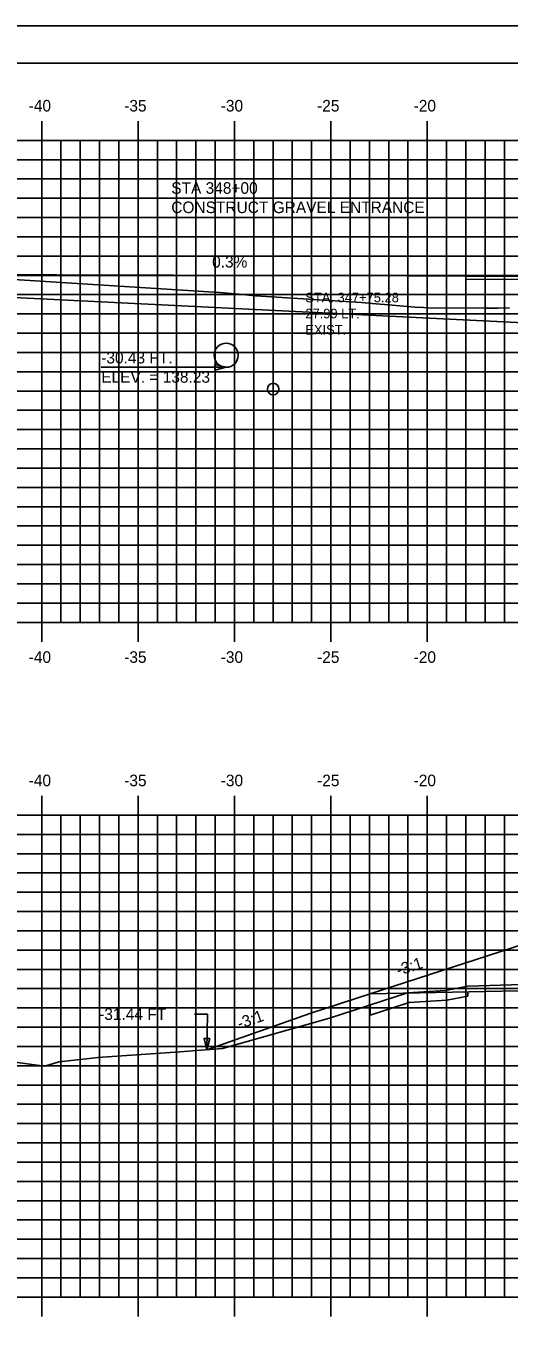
# Model space of a CAD drawing. Extents: x 1144085 to 1144255, y 608981 to 609091.
# Drawn here: x 1144127.5 to 1144152.6, y 609024.1 to 609091.3 of the extents above; entities that cross this region are included whole.
import ezdxf

# ---------------------------------------------------------------- set-up
doc = ezdxf.new("R2010")
doc.units = 0
for name, color, linetype in [('ANNOTATION', 7, 'Continuous'), ('BORDER', 7, 'Continuous'), ('D_Drainage_Culvert', 7, 'Continuous'), ('D_Roadway_Edge_Shoulder', 7, 'Continuous'), ('D_Roadway_SlopeLines', 7, 'Continuous'), ('D_Roadway_SubGrade', 7, 'Continuous'), ('D_Text_Monospaced', 7, 'Continuous'), ('D_Text_Standard', 7, 'Continuous'), ('H_V ANNOTATION', 7, 'Continuous'), ('MAJOR', 7, 'Continuous'), ('MINOR', 7, 'Continuous'), ('PLOT BOUNDARY', 7, 'Continuous'), ('S_Drainage_Invert', 7, 'Continuous'), ('S_Roadway_Centerline', 7, 'Continuous')]:
    doc.layers.add(name, color=color, linetype=linetype)

msp = doc.modelspace()

# ---------------------------------------------------------------- linework, layer by layer
for points in [[(1144123.068, 609078.385), (1144153.349, 609078.292), (1144157.349, 609078.452), (1144168.349, 609078.672), (1144179.349, 609078.452), (1144188.751, 609078.076), (1144196.129, 609075.617), (1144199.129, 609074.617), (1144217.63, 609068.45)], [(1144136.907, 609038.164), (1144142.311, 609040.063), (1144145.395, 609041.063), (1144153.348, 609043.642), (1144153.349, 609043.642), (1144157.349, 609043.802), (1144168.349, 609044.022), (1144179.349, 609043.802), (1144190.025, 609043.375), (1144197.322, 609040.943), (1144200.322, 609039.943), (1144215.637, 609034.838)]]:
    msp.add_lwpolyline(points)
at = {"layer": 'BORDER'}
msp.add_lwpolyline([(1144093.349, 608984.335), (1144253.349, 608984.335), (1144253.349, 609089.335), (1144093.349, 609089.335)], close=True, dxfattribs=at)
at = {"layer": 'D_Drainage_Culvert'}
msp.add_circle((1144137.919, 609074.19), 0.625, dxfattribs=at)
at = {"layer": 'D_Roadway_Edge_Shoulder'}
msp.add_lwpolyline([(1144153.349, 609078.292), (1144150.349, 609078.301), (1144150.349, 609078.135), (1144153.349, 609078.126)], close=True, dxfattribs=at)
at = {"layer": 'D_Roadway_SlopeLines'}
for p, q in [((1144150.45, 609041.164), (1144150.45, 609040.948)), ((1144145.395, 609040.49), (1144145.395, 609039.966))]:
    msp.add_line(p, q, dxfattribs=at)
for points in [[(1144145.395, 609041.063), (1144142.311, 609040.063)], [(1144145.395, 609039.966), (1144147.415, 609040.623), (1144149.357, 609040.737), (1144150.45, 609040.948)], [(1144142.311, 609040.063), (1144136.907, 609038.164)]]:
    msp.add_lwpolyline(points, dxfattribs=at)
at = {"layer": 'D_Roadway_SubGrade'}
for points in [[(1144123.068, 609077.385), (1144153.349, 609075.872), (1144157.349, 609075.952), (1144157.349, 609078.036), (1144157.349, 609078.202), (1144153.349, 609078.042), (1144153.349, 609078.292), (1144123.068, 609078.385)], [(1144157.349, 609043.386), (1144157.349, 609043.552), (1144153.349, 609043.392), (1144153.349, 609043.642), (1144153.348, 609043.642), (1144145.395, 609041.063), (1144157.349, 609041.302)]]:
    msp.add_lwpolyline(points, close=True, dxfattribs=at)
at = {"layer": 'D_Text_Standard'}
msp.add_line((1144131.438, 609073.565), (1144136.238, 609073.565), dxfattribs=at)
for points in [[(1144137.919, 609073.565), (1144136.918, 609073.565), (1144136.238, 609073.565)], [(1144136.907, 609038.164), (1144136.95, 609040.013), (1144136.27, 609040.013)]]:
    msp.add_lwpolyline(points, dxfattribs=at)
for points in [[(1144137.919, 609073.565), (1144137.337, 609073.42), (1144137.337, 609073.711)], [(1144136.907, 609038.164), (1144136.775, 609038.749), (1144137.066, 609038.742)]]:
    msp.add_lwpolyline(points, close=True, dxfattribs=at)
at = {"layer": 'MAJOR'}
for p, q in [((1144128.349, 609086.337), (1144128.349, 609085.335)), ((1144133.349, 609086.337), (1144133.349, 609085.335)), ((1144138.349, 609086.337), (1144138.349, 609085.335)), ((1144143.349, 609086.337), (1144143.349, 609085.335)), ((1144148.349, 609086.337), (1144148.349, 609085.335)), ((1144098.349, 609085.335), (1144238.349, 609085.335)), ((1144098.349, 609085.335), (1144238.349, 609085.335)), ((1144128.349, 609060.335), (1144128.349, 609085.335)), ((1144133.349, 609060.335), (1144133.349, 609085.335)), ((1144138.349, 609060.335), (1144138.349, 609085.335)), ((1144143.349, 609060.335), (1144143.349, 609085.335)), ((1144148.349, 609060.335), (1144148.349, 609085.335)), ((1144098.349, 609080.335), (1144238.349, 609080.335)), ((1144098.349, 609075.335), (1144238.349, 609075.335)), ((1144098.349, 609070.335), (1144238.349, 609070.335)), ((1144098.349, 609065.335), (1144238.349, 609065.335)), ((1144098.349, 609060.335), (1144238.349, 609060.335)), ((1144098.349, 609060.335), (1144238.349, 609060.335)), ((1144128.349, 609059.333), (1144128.349, 609060.335)), ((1144133.349, 609059.333), (1144133.349, 609060.335)), ((1144138.349, 609059.333), (1144138.349, 609060.335)), ((1144143.349, 609059.333), (1144143.349, 609060.335)), ((1144148.349, 609059.333), (1144148.349, 609060.335)), ((1144128.349, 609051.337), (1144128.349, 609050.335)), ((1144133.349, 609051.337), (1144133.349, 609050.335)), ((1144138.349, 609051.337), (1144138.349, 609050.335)), ((1144143.349, 609051.337), (1144143.349, 609050.335)), ((1144148.349, 609051.337), (1144148.349, 609050.335)), ((1144098.349, 609050.335), (1144238.349, 609050.335)), ((1144098.349, 609050.335), (1144238.349, 609050.335)), ((1144128.349, 609025.335), (1144128.349, 609050.335)), ((1144133.349, 609025.335), (1144133.349, 609050.335)), ((1144138.349, 609025.335), (1144138.349, 609050.335)), ((1144143.349, 609025.335), (1144143.349, 609050.335)), ((1144148.349, 609025.335), (1144148.349, 609050.335)), ((1144098.349, 609045.335), (1144238.349, 609045.335)), ((1144098.349, 609040.335), (1144238.349, 609040.335)), ((1144098.349, 609035.335), (1144238.349, 609035.335)), ((1144098.349, 609030.335), (1144238.349, 609030.335)), ((1144098.349, 609025.335), (1144238.349, 609025.335)), ((1144098.349, 609025.335), (1144238.349, 609025.335)), ((1144128.349, 609024.333), (1144128.349, 609025.335)), ((1144133.349, 609024.333), (1144133.349, 609025.335)), ((1144138.349, 609024.333), (1144138.349, 609025.335)), ((1144143.349, 609024.333), (1144143.349, 609025.335)), ((1144148.349, 609024.333), (1144148.349, 609025.335))]:
    msp.add_line(p, q, dxfattribs=at)
at = {"layer": 'MINOR'}
for p, q in [((1144129.349, 609060.335), (1144129.349, 609085.335)), ((1144130.349, 609060.335), (1144130.349, 609085.335)), ((1144131.349, 609060.335), (1144131.349, 609085.335)), ((1144132.349, 609060.335), (1144132.349, 609085.335)), ((1144134.349, 609060.335), (1144134.349, 609085.335)), ((1144135.349, 609060.335), (1144135.349, 609085.335)), ((1144136.349, 609060.335), (1144136.349, 609085.335)), ((1144137.349, 609060.335), (1144137.349, 609085.335)), ((1144139.349, 609060.335), (1144139.349, 609085.335)), ((1144140.349, 609060.335), (1144140.349, 609085.335)), ((1144141.349, 609060.335), (1144141.349, 609085.335)), ((1144142.349, 609060.335), (1144142.349, 609085.335)), ((1144144.349, 609060.335), (1144144.349, 609085.335)), ((1144145.349, 609060.335), (1144145.349, 609085.335)), ((1144146.349, 609060.335), (1144146.349, 609085.335)), ((1144147.349, 609060.335), (1144147.349, 609085.335)), ((1144149.349, 609060.335), (1144149.349, 609085.335)), ((1144150.349, 609060.335), (1144150.349, 609085.335)), ((1144151.349, 609060.335), (1144151.349, 609085.335)), ((1144152.349, 609060.335), (1144152.349, 609085.335)), ((1144098.349, 609084.335), (1144238.349, 609084.335)), ((1144098.349, 609083.335), (1144238.349, 609083.335)), ((1144098.349, 609082.335), (1144238.349, 609082.335)), ((1144098.349, 609081.335), (1144238.349, 609081.335)), ((1144098.349, 609079.335), (1144238.349, 609079.335)), ((1144098.349, 609078.335), (1144238.349, 609078.335)), ((1144098.349, 609077.335), (1144238.349, 609077.335)), ((1144098.349, 609076.335), (1144238.349, 609076.335)), ((1144098.349, 609074.335), (1144238.349, 609074.335)), ((1144098.349, 609073.335), (1144238.349, 609073.335)), ((1144098.349, 609072.335), (1144238.349, 609072.335)), ((1144098.349, 609071.335), (1144238.349, 609071.335)), ((1144098.349, 609069.335), (1144238.349, 609069.335)), ((1144098.349, 609068.335), (1144238.349, 609068.335)), ((1144098.349, 609067.335), (1144238.349, 609067.335)), ((1144098.349, 609066.335), (1144238.349, 609066.335)), ((1144098.349, 609064.335), (1144238.349, 609064.335)), ((1144098.349, 609063.335), (1144238.349, 609063.335)), ((1144098.349, 609062.335), (1144238.349, 609062.335)), ((1144098.349, 609061.335), (1144238.349, 609061.335)), ((1144129.349, 609025.335), (1144129.349, 609050.335)), ((1144130.349, 609025.335), (1144130.349, 609050.335)), ((1144131.349, 609025.335), (1144131.349, 609050.335)), ((1144132.349, 609025.335), (1144132.349, 609050.335)), ((1144134.349, 609025.335), (1144134.349, 609050.335)), ((1144135.349, 609025.335), (1144135.349, 609050.335)), ((1144136.349, 609025.335), (1144136.349, 609050.335)), ((1144137.349, 609025.335), (1144137.349, 609050.335)), ((1144139.349, 609025.335), (1144139.349, 609050.335)), ((1144140.349, 609025.335), (1144140.349, 609050.335)), ((1144141.349, 609025.335), (1144141.349, 609050.335)), ((1144142.349, 609025.335), (1144142.349, 609050.335)), ((1144144.349, 609025.335), (1144144.349, 609050.335)), ((1144145.349, 609025.335), (1144145.349, 609050.335)), ((1144146.349, 609025.335), (1144146.349, 609050.335)), ((1144147.349, 609025.335), (1144147.349, 609050.335)), ((1144149.349, 609025.335), (1144149.349, 609050.335)), ((1144150.349, 609025.335), (1144150.349, 609050.335)), ((1144151.349, 609025.335), (1144151.349, 609050.335)), ((1144152.349, 609025.335), (1144152.349, 609050.335)), ((1144098.349, 609049.335), (1144238.349, 609049.335)), ((1144098.349, 609048.335), (1144238.349, 609048.335)), ((1144098.349, 609047.335), (1144238.349, 609047.335)), ((1144098.349, 609046.335), (1144238.349, 609046.335)), ((1144098.349, 609044.335), (1144238.349, 609044.335)), ((1144098.349, 609043.335), (1144238.349, 609043.335)), ((1144098.349, 609042.335), (1144238.349, 609042.335)), ((1144098.349, 609041.335), (1144238.349, 609041.335)), ((1144098.349, 609039.335), (1144238.349, 609039.335)), ((1144098.349, 609038.335), (1144238.349, 609038.335)), ((1144098.349, 609037.335), (1144238.349, 609037.335)), ((1144098.349, 609036.335), (1144238.349, 609036.335)), ((1144098.349, 609034.335), (1144238.349, 609034.335)), ((1144098.349, 609033.335), (1144238.349, 609033.335)), ((1144098.349, 609032.335), (1144238.349, 609032.335)), ((1144098.349, 609031.335), (1144238.349, 609031.335)), ((1144098.349, 609029.335), (1144238.349, 609029.335)), ((1144098.349, 609028.335), (1144238.349, 609028.335)), ((1144098.349, 609027.335), (1144238.349, 609027.335)), ((1144098.349, 609026.335), (1144238.349, 609026.335))]:
    msp.add_line(p, q, dxfattribs=at)
at = {"layer": 'PLOT BOUNDARY'}
msp.add_lwpolyline([(1144085.256, 608981.276), (1144255.256, 608981.276), (1144255.256, 609091.276), (1144085.256, 609091.276)], close=True, dxfattribs=at)
at = {"layer": 'S_Drainage_Invert'}
msp.add_circle((1144140.359, 609072.44), 0.3, dxfattribs=at)
at = {"layer": 'S_Roadway_Centerline'}
for points in [[(1144126.071, 609078.177), (1144137.012, 609077.48), (1144137.577, 609077.438), (1144138.591, 609077.353), (1144139.444, 609077.274), (1144144.945, 609076.93), (1144145.68, 609076.863), (1144146.127, 609076.822), (1144146.92, 609076.752), (1144147.725, 609076.691), (1144148.16, 609076.665), (1144148.408, 609076.655), (1144151.408, 609076.635), (1144152.016, 609076.628), (1144152.614, 609076.656)], [(1144126.454, 609037.587), (1144128.501, 609037.315), (1144129.255, 609037.532), (1144130.973, 609037.736), (1144131.266, 609037.758), (1144135.518, 609038.06), (1144137.734, 609038.225), (1144143.271, 609039.799), (1144147.322, 609041.116), (1144149.295, 609041.232), (1144150.45, 609041.455), (1144156.669, 609041.645), (1144161.807, 609041.922), (1144167.699, 609041.655), (1144172.025, 609041.53), (1144174.185, 609041.13), (1144175.974, 609040.912), (1144181.368, 609038.355), (1144184.046, 609037.211), (1144194.528, 609036.383), (1144201.114, 609035.654)]]:
    msp.add_lwpolyline(points, dxfattribs=at)

# ---------------------------------------------------------------- texts
at = {"layer": 'ANNOTATION'}
for s, p in [('STA 348+00', (1144135.07, 609082.567)), ('CONSTRUCT GRAVEL ENTRANCE', (1144135.07, 609081.565))]:
    msp.add_text(s, height=0.6, dxfattribs=at).set_placement(p)
for s, rotation, p in [('0.3%', 359.8252, (1144137.19, 609078.742)), ('-3:1', 17.96614, (1144146.853, 609041.987)), ('-3:1', 19.36486, (1144138.614, 609039.224))]:
    msp.add_text(s, height=0.6, rotation=rotation, dxfattribs=at).set_placement(p)
at = {"layer": 'D_Text_Monospaced'}
for s, height, p in [('STA. 347+75.28', 0.49998, (1144142.026, 609076.938)), ('27.99 LT.', 0.5, (1144142.026, 609076.104)), ('EXIST. ', 0.5, (1144142.026, 609075.264))]:
    msp.add_text(s, height=height, dxfattribs=at).set_placement(p)
at = {"layer": 'D_Text_Standard'}
for s, p in [('-30.43 FT.', (1144131.438, 609073.765)), ('ELEV. = 138.23', (1144131.438, 609072.765)), ('-31.44 FT', (1144131.33, 609039.713))]:
    msp.add_text(s, height=0.6, dxfattribs=at).set_placement(p)
at = {"layer": 'H_V ANNOTATION'}
for s, p in [('-40', (1144127.675, 609086.835)), ('-35', (1144132.629, 609086.835)), ('-30', (1144137.637, 609086.835)), ('-25', (1144142.635, 609086.835)), ('-20', (1144147.643, 609086.835)), ('-40', (1144127.675, 609058.235)), ('-35', (1144132.629, 609058.235)), ('-30', (1144137.637, 609058.235)), ('-25', (1144142.635, 609058.235)), ('-20', (1144147.643, 609058.235)), ('-40', (1144127.675, 609051.835)), ('-35', (1144132.629, 609051.835)), ('-30', (1144137.637, 609051.835)), ('-25', (1144142.635, 609051.835)), ('-20', (1144147.643, 609051.835))]:
    msp.add_text(s, height=0.6, dxfattribs=at).set_placement(p)

doc.saveas('drawing.dxf')
